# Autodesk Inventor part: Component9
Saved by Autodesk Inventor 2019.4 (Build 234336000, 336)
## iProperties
Created: 2020-06
Part Number: Component9
Material: Generic
Document SubType Name: Modeling
Designer: Administrator
Density: 1 g/cm^3
Appearance: Default
Title: Component9
Author: Administrator
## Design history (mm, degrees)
